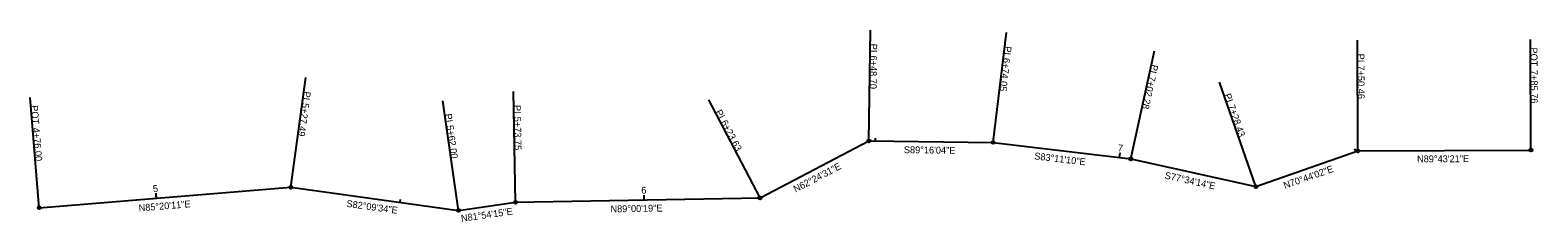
# Model space of a CAD drawing. Extents: x 2342482 to 2342790, y 654910 to 654948.
import ezdxf

# ---------------------------------------------------------------- set-up
doc = ezdxf.new("R2010")
doc.units = 0
for name, color, linetype in [('DR_X_Culvert', 7, 'Continuous'), ('DR_X_Text', 7, 'Continuous'), ('DT_X_Break_Line', 7, 'Continuous'), ('DT_X_Contour_Major', 7, 'Continuous'), ('DT_X_Island', 7, 'Continuous'), ('DT_X_TIN_Hull', 7, 'Continuous'), ('RD_X_GR_Bar', 7, 'Continuous'), ('RD_X_GR_Rt', 7, 'Continuous'), ('SV_X_Terrain_Boundary', 7, 'Continuous'), ('VG_X_Text', 7, 'Continuous')]:
    doc.layers.add(name, color=color, linetype=linetype)

msp = doc.modelspace()

# ---------------------------------------------------------------- linework, layer by layer
at = {"layer": 'DR_X_Text'}
for p, q in [((2342653.13, 654925.98), (2342653.42, 654948.48)), ((2342678.48, 654925.66), (2342681.15, 654948)), ((2342752.84, 654923.95), (2342752.74, 654946.45)), ((2342788.14, 654924.12), (2342788.03, 654946.62)), ((2342706.5, 654922.31), (2342711.35, 654944.28)), ((2342535.22, 654916.56), (2342538.28, 654938.85)), ((2342732.05, 654916.68), (2342724.62, 654937.92)), ((2342483.9, 654912.38), (2342482.07, 654934.8)), ((2342569.41, 654911.85), (2342566.24, 654934.13)), ((2342581.04, 654913.51), (2342580.65, 654936)), ((2342630.91, 654914.37), (2342620.49, 654934.32))]:
    msp.add_line(p, q, dxfattribs=at)
for centre in [(2342653.13, 654925.98), (2342678.48, 654925.66), (2342752.84, 654923.95), (2342788.14, 654924.12), (2342706.5, 654922.31), (2342535.22, 654916.56), (2342732.05, 654916.68), (2342483.9, 654912.38), (2342569.41, 654911.85), (2342581.04, 654913.51), (2342630.91, 654914.37)]:
    msp.add_circle(centre, 0.3, dxfattribs=at)
at = {"layer": 'DT_X_Break_Line'}
for p, q in [((2342704.25, 654922.58), (2342704.32, 654923.18)), ((2342507.82, 654914.33), (2342507.74, 654915.32)), ((2342607.29, 654913.96), (2342607.28, 654914.56))]:
    msp.add_line(p, q, dxfattribs=at)
at = {"layer": 'DT_X_Contour_Major'}
for p, q in [((2342654.43, 654925.97), (2342654.44, 654926.57)), ((2342752.41, 654923.8), (2342752.21, 654924.37)), ((2342704.25, 654922.58), (2342704.36, 654923.57)), ((2342507.82, 654914.33), (2342507.74, 654915.32)), ((2342607.29, 654913.96), (2342607.27, 654914.96)), ((2342557.52, 654913.49), (2342557.6, 654914.08))]:
    msp.add_line(p, q, dxfattribs=at)
at = {"layer": 'DT_X_Island'}
msp.add_line((2342507.82, 654914.33), (2342507.77, 654914.92), dxfattribs=at)
at = {"layer": 'DT_X_TIN_Hull'}
for p, q in [((2342630.91, 654914.37), (2342653.13, 654925.98)), ((2342653.13, 654925.98), (2342678.48, 654925.66)), ((2342678.48, 654925.66), (2342706.5, 654922.31)), ((2342752.84, 654923.95), (2342788.14, 654924.12)), ((2342706.5, 654922.31), (2342732.05, 654916.68)), ((2342732.05, 654916.68), (2342752.84, 654923.95)), ((2342483.9, 654912.38), (2342535.22, 654916.56)), ((2342535.22, 654916.56), (2342569.41, 654911.85)), ((2342569.41, 654911.85), (2342581.04, 654913.51)), ((2342581.04, 654913.51), (2342630.91, 654914.37))]:
    msp.add_line(p, q, dxfattribs=at)
at = {"layer": 'RD_X_GR_Rt'}
for p, q in [((2342653.13, 654925.98), (2342653.42, 654948.48)), ((2342678.48, 654925.66), (2342681.15, 654948)), ((2342752.84, 654923.95), (2342752.74, 654946.45)), ((2342788.14, 654924.12), (2342788.03, 654946.62)), ((2342706.5, 654922.31), (2342711.35, 654944.28)), ((2342535.22, 654916.56), (2342538.28, 654938.85)), ((2342732.05, 654916.68), (2342724.62, 654937.92)), ((2342483.9, 654912.38), (2342482.07, 654934.8)), ((2342569.41, 654911.85), (2342566.24, 654934.13)), ((2342581.04, 654913.51), (2342580.65, 654936)), ((2342630.91, 654914.37), (2342620.49, 654934.32))]:
    msp.add_line(p, q, dxfattribs=at)
for centre in [(2342653.13, 654925.98), (2342678.48, 654925.66), (2342752.84, 654923.95), (2342788.14, 654924.12), (2342706.5, 654922.31), (2342535.22, 654916.56), (2342732.05, 654916.68), (2342483.9, 654912.38), (2342569.41, 654911.85), (2342581.04, 654913.51), (2342630.91, 654914.37)]:
    msp.add_circle(centre, 0.3, dxfattribs=at)
at = {"layer": 'VG_X_Text'}
for p, q in [((2342653.13, 654925.98), (2342653.42, 654948.48)), ((2342678.48, 654925.66), (2342681.15, 654948)), ((2342752.84, 654923.95), (2342752.74, 654946.45)), ((2342788.14, 654924.12), (2342788.03, 654946.62)), ((2342706.5, 654922.31), (2342711.35, 654944.28)), ((2342535.22, 654916.56), (2342538.28, 654938.85)), ((2342732.05, 654916.68), (2342724.62, 654937.92)), ((2342483.9, 654912.38), (2342482.07, 654934.8)), ((2342569.41, 654911.85), (2342566.24, 654934.13)), ((2342581.04, 654913.51), (2342580.65, 654936)), ((2342630.91, 654914.37), (2342620.49, 654934.32))]:
    msp.add_line(p, q, dxfattribs=at)
for centre in [(2342653.13, 654925.98), (2342678.48, 654925.66), (2342752.84, 654923.95), (2342788.14, 654924.12), (2342706.5, 654922.31), (2342535.22, 654916.56), (2342732.05, 654916.68), (2342483.9, 654912.38), (2342569.41, 654911.85), (2342581.04, 654913.51), (2342630.91, 654914.37)]:
    msp.add_circle(centre, 0.3, dxfattribs=at)

# ---------------------------------------------------------------- texts
at = {"layer": 'DR_X_Culvert'}
for s, rotation, p in [('S89°16\'04"E', 359.2678, (2342660.24, 654923.49)), ('N62°24\'31"E', 27.5915, (2342638.18, 654915.46)), ('S83°11\'10"E', 353.1861, (2342686.78, 654922.25)), ('N70°44\'02"E', 19.2662, (2342737.96, 654916.21)), ('N89°43\'21"E', 0.2776, (2342764.91, 654921.61)), ('S77°34\'14"E', 347.5706, (2342713.35, 654918.35)), ('N85°20\'11"E', 4.6636, (2342504.25, 654911.63)), ('S82°09\'34"E', 352.1594, (2342546.5, 654912.58)), ('N81°54\'15"E', 8.0958, (2342570.03, 654909.52)), ('N89°00\'19"E', 0.9948, (2342600.43, 654911.44))]:
    msp.add_text(s, height=1.4, rotation=rotation, dxfattribs=at).set_placement(p)
at = {"layer": 'DR_X_Text'}
for s, rotation, p in [('PI', 269.2678, (2342653.41, 654945.75)), ('6+48.70', 269.2678, (2342653.38, 654943.36)), ('6+74.05', 263.1861, (2342680.57, 654942.92)), ('PI', 263.1861, (2342680.85, 654945.29)), ('PI', 270.2776, (2342752.77, 654943.72)), ('POT', 270.2776, (2342788.06, 654944.98)), ('PI', 257.5706, (2342710.78, 654941.61)), ('7+50.46', 270.2776, (2342752.78, 654941.33)), ('7+85.76', 270.2776, (2342788.08, 654940.41)), ('7+02.28', 257.5706, (2342710.27, 654939.27)), ('5+27.49', 262.1594, (2342537.61, 654933.76)), ('PI', 262.1594, (2342537.93, 654936.13)), ('PI', 289.2662, (2342725.55, 654935.34)), ('7+28.43', 289.2662, (2342726.34, 654933.08)), ('POT', 274.6636, (2342482.23, 654933.16)), ('PI', 278.0958, (2342566.65, 654931.42)), ('PI', 270.9948, (2342580.72, 654933.28)), ('5+73.75', 270.9948, (2342580.76, 654930.89)), ('PI', 297.5915, (2342621.78, 654931.9)), ('4+76.00', 274.6636, (2342482.6, 654928.61)), ('5+62.00', 278.0958, (2342566.98, 654929.06)), ('6+23.63', 297.5915, (2342622.89, 654929.78))]:
    msp.add_text(s, height=1.4, rotation=rotation, dxfattribs=at).set_placement(p)
at = {"layer": 'DT_X_Break_Line'}
msp.add_text('5', height=1.4, rotation=4.6636, dxfattribs=at).set_placement((2342507.16, 654915.55))
at = {"layer": 'DT_X_Contour_Major'}
for s, rotation, p in [('7', 353.1861, (2342703.82, 654923.89)), ('5', 4.6636, (2342507.16, 654915.55)), ('6', 0.9948, (2342606.71, 654915.23))]:
    msp.add_text(s, height=1.4, rotation=rotation, dxfattribs=at).set_placement(p)
at = {"layer": 'RD_X_GR_Bar'}
for s, rotation, p in [('S89°16\'04"E', 359.2678, (2342660.24, 654923.49)), ('N62°24\'31"E', 27.5915, (2342638.18, 654915.46)), ('S83°11\'10"E', 353.1861, (2342686.78, 654922.25)), ('N70°44\'02"E', 19.2662, (2342737.96, 654916.21)), ('N89°43\'21"E', 0.2776, (2342764.91, 654921.61)), ('S77°34\'14"E', 347.5706, (2342713.35, 654918.35)), ('N85°20\'11"E', 4.6636, (2342504.25, 654911.63)), ('S82°09\'34"E', 352.1594, (2342546.5, 654912.58)), ('N81°54\'15"E', 8.0958, (2342570.03, 654909.52)), ('N89°00\'19"E', 0.9948, (2342600.43, 654911.44))]:
    msp.add_text(s, height=1.4, rotation=rotation, dxfattribs=at).set_placement(p)
at = {"layer": 'RD_X_GR_Rt'}
for s, rotation, p in [('PI', 269.2678, (2342653.41, 654945.75)), ('6+48.70', 269.2678, (2342653.38, 654943.36)), ('6+74.05', 263.1861, (2342680.57, 654942.92)), ('PI', 263.1861, (2342680.85, 654945.29)), ('PI', 270.2776, (2342752.77, 654943.72)), ('POT', 270.2776, (2342788.06, 654944.98)), ('PI', 257.5706, (2342710.78, 654941.61)), ('7+50.46', 270.2776, (2342752.78, 654941.33)), ('7+85.76', 270.2776, (2342788.08, 654940.41)), ('7+02.28', 257.5706, (2342710.27, 654939.27)), ('5+27.49', 262.1594, (2342537.61, 654933.76)), ('PI', 262.1594, (2342537.93, 654936.13)), ('PI', 289.2662, (2342725.55, 654935.34)), ('7+28.43', 289.2662, (2342726.34, 654933.08)), ('POT', 274.6636, (2342482.23, 654933.16)), ('PI', 278.0958, (2342566.65, 654931.42)), ('PI', 270.9948, (2342580.72, 654933.28)), ('5+73.75', 270.9948, (2342580.76, 654930.89)), ('PI', 297.5915, (2342621.78, 654931.9)), ('4+76.00', 274.6636, (2342482.6, 654928.61)), ('5+62.00', 278.0958, (2342566.98, 654929.06)), ('6+23.63', 297.5915, (2342622.89, 654929.78))]:
    msp.add_text(s, height=1.4, rotation=rotation, dxfattribs=at).set_placement(p)
at = {"layer": 'SV_X_Terrain_Boundary'}
for s, rotation, p in [('S89°16\'04"E', 359.2678, (2342660.24, 654923.49)), ('N62°24\'31"E', 27.5915, (2342638.18, 654915.46)), ('S83°11\'10"E', 353.1861, (2342686.78, 654922.25)), ('N70°44\'02"E', 19.2662, (2342737.96, 654916.21)), ('N89°43\'21"E', 0.2776, (2342764.91, 654921.61)), ('S77°34\'14"E', 347.5706, (2342713.35, 654918.35)), ('N85°20\'11"E', 4.6636, (2342504.25, 654911.63)), ('S82°09\'34"E', 352.1594, (2342546.5, 654912.58)), ('N81°54\'15"E', 8.0958, (2342570.03, 654909.52)), ('N89°00\'19"E', 0.9948, (2342600.43, 654911.44))]:
    msp.add_text(s, height=1.4, rotation=rotation, dxfattribs=at).set_placement(p)
at = {"layer": 'VG_X_Text'}
for s, rotation, p in [('PI', 269.2678, (2342653.41, 654945.75)), ('6+48.70', 269.2678, (2342653.38, 654943.36)), ('6+74.05', 263.1861, (2342680.57, 654942.92)), ('PI', 263.1861, (2342680.85, 654945.29)), ('PI', 270.2776, (2342752.77, 654943.72)), ('POT', 270.2776, (2342788.06, 654944.98)), ('PI', 257.5706, (2342710.78, 654941.61)), ('7+50.46', 270.2776, (2342752.78, 654941.33)), ('7+85.76', 270.2776, (2342788.08, 654940.41)), ('7+02.28', 257.5706, (2342710.27, 654939.27)), ('5+27.49', 262.1594, (2342537.61, 654933.76)), ('PI', 262.1594, (2342537.93, 654936.13)), ('PI', 289.2662, (2342725.55, 654935.34)), ('7+28.43', 289.2662, (2342726.34, 654933.08)), ('POT', 274.6636, (2342482.23, 654933.16)), ('PI', 278.0958, (2342566.65, 654931.42)), ('PI', 270.9948, (2342580.72, 654933.28)), ('5+73.75', 270.9948, (2342580.76, 654930.89)), ('PI', 297.5915, (2342621.78, 654931.9)), ('4+76.00', 274.6636, (2342482.6, 654928.61)), ('5+62.00', 278.0958, (2342566.98, 654929.06)), ('6+23.63', 297.5915, (2342622.89, 654929.78))]:
    msp.add_text(s, height=1.4, rotation=rotation, dxfattribs=at).set_placement(p)

doc.saveas('drawing.dxf')
